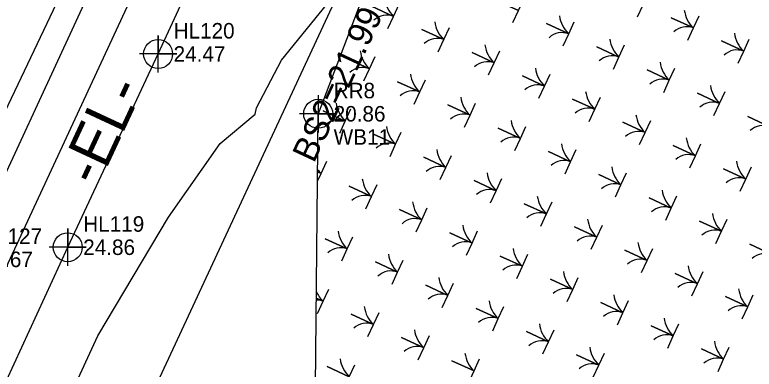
# Model space of a CAD drawing. Extents: x 2532037 to 2533565, y 713396 to 716867.
# Drawn here: x 2532822.3 to 2532941.6, y 715515.5 to 715572.7 of the extents above; entities that cross this region are included whole.
import ezdxf

# ---------------------------------------------------------------- set-up
doc = ezdxf.new("R2010")
doc.units = 0
for name, color, linetype in [('Exist Environmental Wetland Boundary', 7, 'Continuous'), ('Exist Environmental Wetland Boundary Cogo Comment', 7, 'Continuous'), ('Exist Environmental Wetland Boundary Cogo Elevation', 7, 'Continuous'), ('Exist Environmental Wetland Boundary Cogo Number', 7, 'Continuous'), ('Exist Environmental Wetland Boundary Cogo Point CELL', 7, 'Continuous'), ('Exist Horizontal Alignment', 7, 'Continuous'), ('Exist Horizontal Alignment Direction Label', 7, 'Continuous'), ('Exist Hydro Stream or Body of Water', 7, 'Continuous'), ('Exist Property Line Text', 7, 'Continuous'), ('Exist Right of Way Line', 7, 'Continuous'), ('Exist Roads Soil', 7, 'Continuous'), ('Exist Roads Soil Cogo Elevation', 7, 'Continuous'), ('Exist Roads Soil Cogo Number', 7, 'Continuous'), ('Exist Roads Soil Cogo Point CELL', 7, 'Continuous'), ('Exist Structure Major Bridge Seat Top Elevation', 7, 'Continuous'), ('Exist Utilities Telephone UG Cable SUE LOS C', 7, 'Continuous'), ('Scratch_Level_1', 7, 'Continuous')]:
    doc.layers.add(name, color=color, linetype=linetype)

msp = doc.modelspace()

# ---------------------------------------------------------------- linework, layer by layer
at = {"layer": 'Exist Environmental Wetland Boundary'}
for p in [(2532884.97, 715592.7), (2532870.62, 715493.75)]:
    msp.add_line(p, (2532871.25, 715556.68), dxfattribs=at)
at = {"layer": 'Exist Environmental Wetland Boundary Cogo Point CELL'}
msp.add_lwpolyline([(2532871.25, 715559.68), (2532871.25, 715553.68), (2532871.25, 715556.68), (2532874.25, 715556.68), (2532868.25, 715556.68)], dxfattribs=at)
msp.add_circle((2532871.25, 715556.68), 2.34, dxfattribs=at)
at = {"layer": 'Exist Horizontal Alignment'}
msp.add_line((2532720.82, 715316.86), (2532922.84, 715751.08), dxfattribs=at)
at = {"layer": 'Exist Hydro Stream or Body of Water'}
msp.add_lwpolyline([(2532802.27, 715448.15), (2532818.09, 715482.8), (2532835.7, 715520.84), (2532847.1, 715539.97), (2532855.45, 715551.87), (2532861.07, 715556.64), (2532861.28, 715557.62), (2532865.35, 715565.35), (2532877.49, 715580.36), (2532883.64, 715600.48), (2532881.52, 715610.88), (2532882.29, 715614.35)], dxfattribs=at)
at = {"layer": 'Exist Right of Way Line'}
msp.add_line((2532748.02, 715304.21), (2532950.04, 715738.43), dxfattribs=at)
at = {"layer": 'Exist Roads Soil'}
for points in [[(2532854.21, 715621.57), (2532849.63, 715612.83), (2532840.29, 715590.95), (2532834.77, 715577.32), (2532814.33, 715533.18), (2532796.18, 715493.99), (2532779.84, 715458.92), (2532764.58, 715425.8), (2532746.47, 715387.06), (2532729.42, 715351.71), (2532714.48, 715319.9), (2532706.79, 715303.32)], [(2532718.48, 715296.34), (2532722.41, 715303.93), (2532737.17, 715334.72), (2532753.88, 715369.29), (2532769.73, 715403.73), (2532784.98, 715435.43), (2532799.77, 715466.71), (2532814.69, 715500.17), (2532830.82, 715535.14), (2532845.41, 715566.33), (2532858.27, 715594.22), (2532867.39, 715615.56), (2532854.21, 715621.57)]]:
    msp.add_lwpolyline(points, dxfattribs=at)
at = {"layer": 'Exist Roads Soil Cogo Point CELL'}
for points in [[(2532845.41, 715563.33), (2532845.41, 715569.33), (2532845.41, 715566.33), (2532848.41, 715566.33), (2532842.41, 715566.33)], [(2532830.82, 715532.14), (2532830.82, 715538.14), (2532830.82, 715535.14), (2532833.82, 715535.14), (2532827.82, 715535.14)]]:
    msp.add_lwpolyline(points, dxfattribs=at)
for centre in [(2532845.41, 715566.33), (2532830.82, 715535.14)]:
    msp.add_circle(centre, 2.34, dxfattribs=at)
at = {"layer": 'Exist Utilities Telephone UG Cable SUE LOS C'}
msp.add_lwpolyline([(2532724.2, 715351.24), (2532725.33, 715353.66), (2532742.38, 715389), (2532760.47, 715427.7), (2532775.73, 715460.82), (2532792.08, 715495.9), (2532810.22, 715535.08), (2532832.17, 715581.2), (2532835.87, 715586.71), (2532839.77, 715591.39), (2532844.32, 715594.26), (2532854.86, 715595.72), (2532862.76, 715593.88), (2532871.08, 715591.56), (2532871.08, 715591.56)], dxfattribs=at)
at = {"layer": 'Scratch_Level_1'}
for points in [[(2532922.81, 715572.33), (2532923.71, 715574.29), (2532920.13, 715575.94), (2532923.71, 715574.29), (2532924.61, 715576.24)], [(2532902.66, 715571.39), (2532903.57, 715573.34), (2532899.98, 715574.99), (2532903.57, 715573.34), (2532904.47, 715575.29)], [(2532882.52, 715570.44), (2532883.42, 715572.4), (2532879.84, 715574.05), (2532883.42, 715572.4), (2532884.33, 715574.35)], [(2532930.93, 715568.58), (2532931.83, 715570.54), (2532928.25, 715572.19), (2532931.83, 715570.54), (2532932.73, 715572.49)], [(2532910.79, 715567.64), (2532911.69, 715569.59), (2532908.11, 715571.24), (2532911.69, 715569.59), (2532912.59, 715571.54)], [(2532890.64, 715566.69), (2532891.55, 715568.65), (2532887.96, 715570.3), (2532891.55, 715568.65), (2532892.45, 715570.6)], [(2532939.05, 715564.84), (2532939.95, 715566.79), (2532936.37, 715568.44), (2532939.95, 715566.79), (2532940.85, 715568.74)], [(2532918.91, 715563.89), (2532919.81, 715565.84), (2532916.23, 715567.5), (2532919.81, 715565.84), (2532920.71, 715567.79)], [(2532898.77, 715562.94), (2532899.67, 715564.9), (2532896.09, 715566.55), (2532899.67, 715564.9), (2532900.57, 715566.85)], [(2532878.62, 715562), (2532879.53, 715563.95), (2532875.94, 715565.6), (2532879.53, 715563.95), (2532880.43, 715565.9)], [(2532927.03, 715560.14), (2532927.93, 715562.09), (2532924.35, 715563.75), (2532927.93, 715562.09), (2532928.83, 715564.04)], [(2532906.89, 715559.19), (2532907.79, 715561.15), (2532904.21, 715562.8), (2532907.79, 715561.15), (2532908.69, 715563.1)], [(2532886.75, 715558.25), (2532887.65, 715560.2), (2532884.07, 715561.85), (2532887.65, 715560.2), (2532888.55, 715562.15)], [(2532915.01, 715555.45), (2532915.91, 715557.4), (2532912.33, 715559.05), (2532915.91, 715557.4), (2532916.81, 715559.35)], [(2532935.15, 715556.39), (2532936.05, 715558.34), (2532932.47, 715560), (2532936.05, 715558.34), (2532936.95, 715560.3)], [(2532894.87, 715554.5), (2532895.77, 715556.45), (2532892.19, 715558.11), (2532895.77, 715556.45), (2532896.67, 715558.4)], [(2532874.73, 715553.55), (2532875.63, 715555.51), (2532872.05, 715557.16), (2532875.63, 715555.51), (2532876.53, 715557.46)], [(2532943.27, 715552.64), (2532944.17, 715554.59), (2532940.59, 715556.25), (2532944.17, 715554.59), (2532945.07, 715556.55)], [(2532902.99, 715550.75), (2532903.89, 715552.7), (2532900.31, 715554.36), (2532903.89, 715552.7), (2532904.79, 715554.65)], [(2532923.13, 715551.7), (2532924.03, 715553.65), (2532920.45, 715555.3), (2532924.03, 715553.65), (2532924.93, 715555.6)], [(2532882.85, 715549.8), (2532883.75, 715551.76), (2532880.17, 715553.41), (2532883.75, 715551.76), (2532884.65, 715553.71)], [(2532911.11, 715547), (2532912.01, 715548.95), (2532908.43, 715550.61), (2532912.01, 715548.95), (2532912.91, 715550.91)], [(2532931.25, 715547.95), (2532932.15, 715549.9), (2532928.57, 715551.55), (2532932.15, 715549.9), (2532933.05, 715551.85)], [(2532890.97, 715546.06), (2532891.87, 715548.01), (2532888.29, 715549.66), (2532891.87, 715548.01), (2532892.77, 715549.96)], [(2532871.16, 715547.33), (2532871.73, 715547.06), (2532872.63, 715549.01)], [(2532871.14, 715545.79), (2532871.73, 715547.06), (2532871.16, 715547.33)], [(2532939.37, 715544.2), (2532940.27, 715546.15), (2532936.69, 715547.8), (2532940.27, 715546.15), (2532941.18, 715548.1)], [(2532899.09, 715542.31), (2532899.99, 715544.26), (2532896.41, 715545.91), (2532899.99, 715544.26), (2532900.89, 715546.21)], [(2532919.23, 715543.25), (2532920.13, 715545.2), (2532916.55, 715546.86), (2532920.13, 715545.2), (2532921.03, 715547.16)], [(2532878.95, 715541.36), (2532879.85, 715543.31), (2532876.27, 715544.97), (2532879.85, 715543.31), (2532880.75, 715545.27)], [(2532927.35, 715539.5), (2532928.25, 715541.45), (2532924.67, 715543.11), (2532928.25, 715541.45), (2532929.16, 715543.41)], [(2532887.07, 715537.61), (2532887.97, 715539.56), (2532884.39, 715541.22), (2532887.97, 715539.56), (2532888.87, 715541.52)], [(2532907.21, 715538.56), (2532908.11, 715540.51), (2532904.53, 715542.16), (2532908.11, 715540.51), (2532909.01, 715542.46)], [(2532935.47, 715535.75), (2532936.38, 715537.71), (2532932.79, 715539.36), (2532936.38, 715537.71), (2532937.28, 715539.66)], [(2532895.19, 715533.86), (2532896.09, 715535.81), (2532892.51, 715537.47), (2532896.09, 715535.81), (2532896.99, 715537.77)], [(2532915.33, 715534.81), (2532916.23, 715536.76), (2532912.65, 715538.41), (2532916.23, 715536.76), (2532917.14, 715538.71)], [(2532875.05, 715532.92), (2532875.95, 715534.87), (2532872.37, 715536.52), (2532875.95, 715534.87), (2532876.85, 715536.82)], [(2532943.6, 715532), (2532944.5, 715533.96), (2532940.92, 715535.61), (2532944.5, 715533.96), (2532945.4, 715535.91)], [(2532923.45, 715531.06), (2532924.36, 715533.01), (2532920.77, 715534.66), (2532924.36, 715533.01), (2532925.26, 715534.96)], [(2532883.17, 715529.17), (2532884.07, 715531.12), (2532880.49, 715532.77), (2532884.07, 715531.12), (2532884.97, 715533.07)], [(2532903.31, 715530.11), (2532904.21, 715532.06), (2532900.63, 715533.72), (2532904.21, 715532.06), (2532905.12, 715534.02)], [(2532931.58, 715527.31), (2532932.48, 715529.26), (2532928.9, 715530.91), (2532932.48, 715529.26), (2532933.38, 715531.21)], [(2532911.44, 715526.36), (2532912.34, 715528.32), (2532908.75, 715529.97), (2532912.34, 715528.32), (2532913.24, 715530.27)], [(2532870.95, 715526.93), (2532872.05, 715526.42), (2532872.96, 715528.38)], [(2532891.29, 715525.42), (2532892.2, 715527.37), (2532888.61, 715529.02), (2532892.2, 715527.37), (2532893.1, 715529.32)], [(2532939.7, 715523.56), (2532940.6, 715525.51), (2532937.02, 715527.17), (2532940.6, 715525.51), (2532941.5, 715527.46)], [(2532871.15, 715524.47), (2532872.05, 715526.42), (2532870.95, 715526.93)], [(2532919.56, 715522.61), (2532920.46, 715524.57), (2532916.88, 715526.22), (2532920.46, 715524.57), (2532921.36, 715526.52)], [(2532879.27, 715520.72), (2532880.18, 715522.67), (2532876.59, 715524.33), (2532880.18, 715522.67), (2532881.08, 715524.63)], [(2532899.42, 715521.67), (2532900.32, 715523.62), (2532896.73, 715525.27), (2532900.32, 715523.62), (2532901.22, 715525.57)], [(2532927.68, 715518.86), (2532928.58, 715520.82), (2532925, 715522.47), (2532928.58, 715520.82), (2532929.48, 715522.77)], [(2532907.54, 715517.92), (2532908.44, 715519.87), (2532904.86, 715521.52), (2532908.44, 715519.87), (2532909.34, 715521.82)], [(2532887.4, 715516.97), (2532888.3, 715518.93), (2532884.71, 715520.58), (2532888.3, 715518.93), (2532889.2, 715520.88)], [(2532935.8, 715515.11), (2532936.7, 715517.07), (2532933.12, 715518.72), (2532936.7, 715517.07), (2532937.6, 715519.02)], [(2532915.66, 715514.17), (2532916.56, 715516.12), (2532912.98, 715517.78), (2532916.56, 715516.12), (2532917.46, 715518.07)], [(2532895.52, 715513.22), (2532896.42, 715515.18), (2532892.84, 715516.83), (2532896.42, 715515.18), (2532897.32, 715517.13)], [(2532875.38, 715512.28), (2532876.28, 715514.23), (2532872.69, 715515.88), (2532876.28, 715514.23), (2532877.18, 715516.18)]]:
    msp.add_lwpolyline(points, dxfattribs=at)
for centre, radius, start, end in [((2532886.71, 715575.9), 4.81, 187.3464, 226.8412), ((2532882.34, 715569.52), 3.07, 69.3593, 132.7539), ((2532914.97, 715573.1), 4.81, 187.3464, 226.8412), ((2532935.12, 715574.04), 4.81, 187.3464, 226.8412), ((2532894.83, 715572.15), 4.81, 187.3464, 226.8412), ((2532930.74, 715567.66), 3.07, 69.3593, 132.7539), ((2532890.46, 715565.77), 3.07, 69.3593, 132.7539), ((2532910.6, 715566.71), 3.07, 69.3593, 132.7539), ((2532923.1, 715569.35), 4.81, 187.3464, 226.8412), ((2532943.24, 715570.29), 4.81, 187.3464, 226.8412), ((2532902.95, 715568.4), 4.81, 187.3464, 226.8412), ((2532882.81, 715567.46), 4.81, 187.3464, 226.8412), ((2532938.87, 715563.91), 3.07, 69.3593, 132.7539), ((2532918.72, 715562.96), 3.07, 69.3593, 132.7539), ((2532878.44, 715561.07), 3.07, 69.3593, 132.7539), ((2532898.58, 715562.02), 3.07, 69.3593, 132.7539), ((2532911.08, 715564.65), 4.81, 187.3464, 226.8412), ((2532931.22, 715565.6), 4.81, 187.3464, 226.8412), ((2532890.93, 715563.71), 4.81, 187.3464, 226.8412), ((2532926.85, 715559.22), 3.07, 69.3593, 132.7539), ((2532886.56, 715557.32), 3.07, 69.3593, 132.7539), ((2532906.71, 715558.27), 3.07, 69.3593, 132.7539), ((2532939.34, 715561.85), 4.81, 187.3464, 226.8412), ((2532899.06, 715559.96), 4.81, 187.3464, 226.8412), ((2532919.2, 715560.9), 4.81, 187.3464, 226.8412), ((2532878.91, 715559.01), 4.81, 187.3464, 226.8412), ((2532934.97, 715555.47), 3.07, 69.3593, 132.7539), ((2532914.83, 715554.52), 3.07, 69.3593, 132.7539), ((2532874.54, 715552.63), 3.07, 69.3593, 132.7539), ((2532894.69, 715553.57), 3.07, 69.3593, 132.7539), ((2532927.32, 715557.15), 4.81, 187.3464, 226.8412), ((2532887.04, 715555.26), 4.81, 187.3464, 226.8412), ((2532907.18, 715556.21), 4.81, 187.3464, 226.8412), ((2532943.09, 715551.72), 3.07, 69.3593, 132.7539), ((2532922.95, 715550.77), 3.07, 69.3593, 132.7539), ((2532902.81, 715549.83), 3.07, 69.3593, 132.7539), ((2532935.44, 715553.4), 4.81, 187.3464, 226.8412), ((2532882.67, 715548.88), 3.07, 69.3593, 132.7539), ((2532895.16, 715551.51), 4.81, 187.3464, 226.8412), ((2532915.3, 715552.46), 4.81, 187.3464, 226.8412), ((2532931.07, 715547.02), 3.07, 69.3593, 132.7539), ((2532910.93, 715546.08), 3.07, 69.3593, 132.7539), ((2532943.56, 715549.66), 4.81, 187.3464, 226.8412), ((2532875.02, 715550.57), 4.81, 216.6417, 226.8412), ((2532890.79, 715545.13), 3.07, 69.3593, 132.7539), ((2532923.42, 715548.71), 4.81, 187.3464, 226.8412), ((2532870.65, 715544.18), 3.07, 69.3593, 80.4481), ((2532883.14, 715546.82), 4.81, 187.3464, 226.8412), ((2532903.28, 715547.76), 4.81, 187.3464, 226.8412), ((2532939.19, 715543.27), 3.07, 69.3593, 132.7539), ((2532919.05, 715542.33), 3.07, 69.3593, 132.7539), ((2532898.91, 715541.38), 3.07, 69.3593, 132.7539), ((2532931.54, 715544.96), 4.81, 187.3464, 226.8412), ((2532878.77, 715540.44), 3.07, 69.3593, 132.7539), ((2532911.4, 715544.01), 4.81, 187.3464, 226.8412), ((2532891.26, 715543.07), 4.81, 187.3464, 226.8412), ((2532927.17, 715538.58), 3.07, 69.3593, 132.7539), ((2532907.03, 715537.63), 3.07, 69.3593, 132.7539), ((2532939.66, 715541.21), 4.81, 187.3464, 226.8412), ((2532886.89, 715536.69), 3.07, 69.3593, 132.7539), ((2532919.52, 715540.27), 4.81, 187.3464, 226.8412), ((2532879.24, 715538.37), 4.81, 187.3464, 226.8412), ((2532899.38, 715539.32), 4.81, 187.3464, 226.8412), ((2532935.29, 715534.83), 3.07, 69.3593, 132.7539), ((2532915.15, 715533.88), 3.07, 69.3593, 132.7539), ((2532895.01, 715532.94), 3.07, 69.3593, 132.7539), ((2532927.64, 715536.52), 4.81, 187.3464, 226.8412), ((2532874.87, 715531.99), 3.07, 69.3593, 132.7539), ((2532907.5, 715535.57), 4.81, 187.3464, 226.8412), ((2532943.41, 715531.08), 3.07, 69.3593, 132.7539), ((2532887.36, 715534.62), 4.81, 187.3464, 226.8412), ((2532923.27, 715530.13), 3.07, 69.3593, 132.7539), ((2532903.13, 715529.19), 3.07, 69.3593, 132.7539), ((2532935.76, 715532.77), 4.81, 187.3464, 226.8412), ((2532882.99, 715528.24), 3.07, 69.3593, 132.7539), ((2532915.62, 715531.82), 4.81, 187.3464, 226.8412), ((2532895.48, 715530.88), 4.81, 187.3464, 226.8412), ((2532931.39, 715526.38), 3.07, 69.3593, 132.7539), ((2532911.25, 715525.44), 3.07, 69.3593, 132.7539), ((2532943.89, 715529.02), 4.81, 187.3464, 226.8412), ((2532875.34, 715529.93), 4.81, 204.3655, 226.8412), ((2532891.11, 715524.49), 3.07, 69.3593, 132.7539), ((2532923.75, 715528.07), 4.81, 187.3464, 226.8412), ((2532870.97, 715523.55), 3.07, 69.3593, 90.3701), ((2532903.6, 715527.13), 4.81, 187.3464, 226.8412), ((2532883.46, 715526.18), 4.81, 187.3464, 226.8412), ((2532919.37, 715521.69), 3.07, 69.3593, 132.7539), ((2532939.52, 715522.63), 3.07, 69.3593, 132.7539), ((2532899.23, 715520.74), 3.07, 69.3593, 132.7539), ((2532931.87, 715524.32), 4.81, 187.3464, 226.8412), ((2532879.09, 715519.8), 3.07, 69.3593, 132.7539), ((2532911.73, 715523.38), 4.81, 187.3464, 226.8412), ((2532891.58, 715522.43), 4.81, 187.3464, 226.8412), ((2532927.5, 715517.94), 3.07, 69.3593, 132.7539), ((2532907.35, 715516.99), 3.07, 69.3593, 132.7539), ((2532939.99, 715520.57), 4.81, 187.3464, 226.8412), ((2532887.21, 715516.05), 3.07, 69.3593, 132.7539), ((2532919.85, 715519.63), 4.81, 187.3464, 226.8412), ((2532899.71, 715518.68), 4.81, 187.3464, 226.8412), ((2532879.56, 715517.74), 4.81, 187.3464, 226.8412), ((2532915.48, 715513.24), 3.07, 69.3593, 132.7539), ((2532935.62, 715514.19), 3.07, 69.3593, 132.7539)]:
    msp.add_arc(centre, radius, start, end, dxfattribs=at)

# ---------------------------------------------------------------- texts
at = {"layer": 'Exist Environmental Wetland Boundary Cogo Comment'}
msp.add_text('WB11', height=2.5, dxfattribs=at).set_placement((2532873.75, 715551.68))
at = {"layer": 'Exist Environmental Wetland Boundary Cogo Elevation'}
msp.add_text('20.86', height=2.5, dxfattribs=at).set_placement((2532873.75, 715555.43))
at = {"layer": 'Exist Environmental Wetland Boundary Cogo Number'}
msp.add_text('RR8', height=2.5, dxfattribs=at).set_placement((2532873.75, 715559.18))
at = {"layer": 'Exist Horizontal Alignment Direction Label'}
msp.add_text('-EL-', height=7, rotation=65.05, dxfattribs=at).set_placement((2532835.66, 715544.73))
at = {"layer": 'Exist Property Line Text'}
msp.add_text('PROPERTY LINE RUNS THE CENTER OF MEADOW BRANCH', height=4, rotation=153.9543, dxfattribs=at).set_placement((2533050.26, 715532.29))
at = {"layer": 'Exist Roads Soil Cogo Elevation'}
for s, p in [('24.47', (2532847.91, 715565.08)), ('24.86', (2532833.32, 715533.89)), ('24.67', (2532816.83, 715531.93))]:
    msp.add_text(s, height=2.5, dxfattribs=at).set_placement(p)
at = {"layer": 'Exist Roads Soil Cogo Number'}
for s, p in [('HL120', (2532847.91, 715568.83)), ('HL119', (2532833.32, 715537.64)), ('HL127', (2532816.83, 715535.68))]:
    msp.add_text(s, height=2.5, dxfattribs=at).set_placement(p)
at = {"layer": 'Exist Structure Major Bridge Seat Top Elevation'}
msp.add_text("BS2=21.99'", height=4, rotation=65.05, dxfattribs=at).set_placement((2532870.56, 715548.59))

doc.saveas('drawing.dxf')
